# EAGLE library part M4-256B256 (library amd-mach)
AMD MACH SERIES
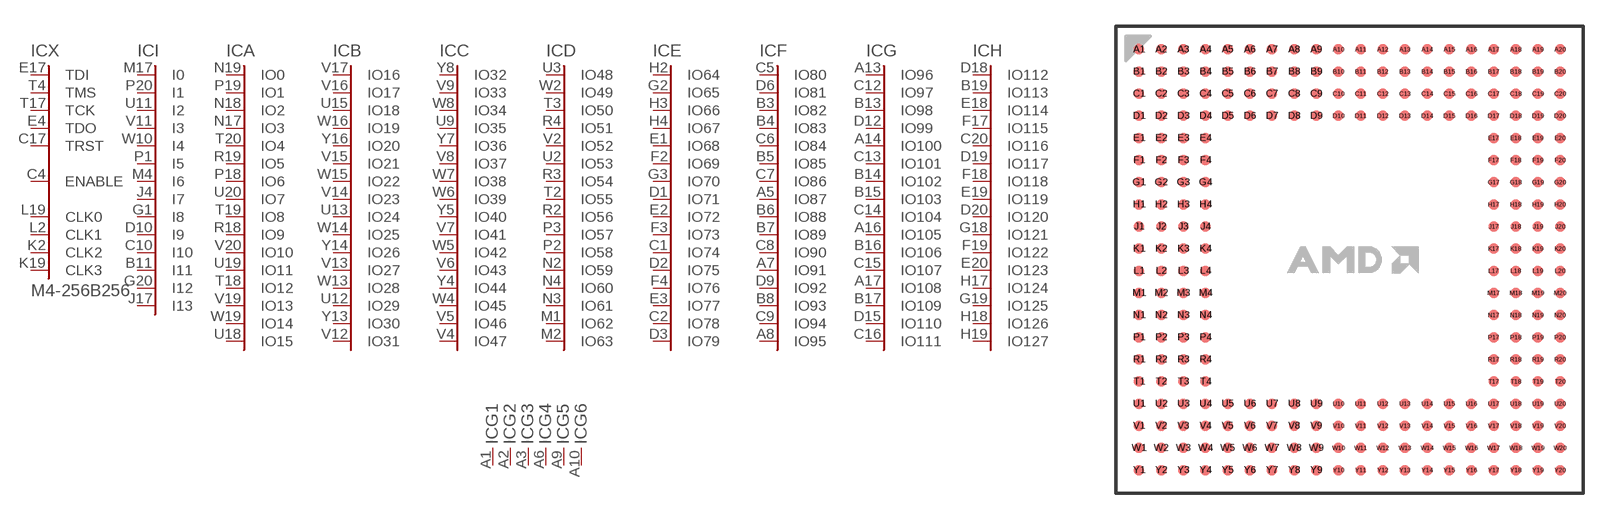
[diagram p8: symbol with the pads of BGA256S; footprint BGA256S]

Designator prefix IC; gates X=M4-256-C A=IO15 B=IO31 C=IO47 D=IO63 E=IO79 F=IO95 G=IO111 H=IO127 I=M4-I13 G1=GND G2=GND G3=GND G4=GND G5=GND G6=GND G7=GND G8=GND G9=GND G10=GND G11=GND G12=GND G13=GND G14=GND G15=GND G16=GND G17=GND G18=GND G19=GND G20=GND G21=GND G22=GND V1=VCC V2=VCC V3=VCC V4=VCC V5=VCC V6=VCC V7=VCC V8=VCC V9=VCC V10=VCC V11=VCC V12=VCC V13=VCC V14=VCC V15=VCC V16=VCC V17=VCC V18=VCC V19=VCC V20=VCC G23=GND G24=GND G25=GND G26=GND G27=GND G28=GND G29=GND G30=GND G31=GND G32=GND NC1=NC NC2=NC NC3=NC NC4=NC NC5=NC NC6=NC NC7=NC NC8=NC NC9=NC NC10=NC NC11=NC NC12=NC NC13=NC NC14=NC NC15=NC NC16=NC NC17=NC NC18=NC NC19=NC NC20=NC NC21=NC NC22=NC NC23=NC NC24=NC NC25=NC NC26=NC NC27=NC NC28=NC NC29=NC NC30=NC NC31=NC NC32=NC NC33=NC NC34=NC NC35=NC NC36=NC NC37=NC NC38=NC NC39=NC NC40=NC NC41=NC NC42=NC NC43=NC NC44=NC NC45=NC NC46=NC NC47=NC NC48=NC G33=GND G34=GND G35=GND G36=GND

## M4-256B256 (OC_FARNELL: unknown; OC_NEWARK: unknown)  [BGA256S]
A1  G1:GND  pwr
A2  G2:GND  pwr
A3  G3:GND  pwr
A4  NC1:NC  nc
A5  F:IO87
A6  G4:GND  pwr
A7  F:IO91
A8  F:IO95
A9  G5:GND  pwr
A10  G6:GND  pwr
A11  G7:GND  pwr
A12  G8:GND  pwr
A13  G:IO96
A14  G:IO100
A15  G9:GND  pwr
A16  G:IO105
A17  G:IO108
A18  G10:GND  pwr
A19  NC2:NC  nc
A20  G11:GND  pwr
B1  G12:GND  pwr
B2  NC3:NC  nc
B3  F:IO82
B4  F:IO83
B5  F:IO85
B6  F:IO88
B7  F:IO89
B8  F:IO93
B9  NC4:NC  nc
B10  NC5:NC  nc
B11  I:I11  in
B12  NC6:NC  nc
B13  G:IO98
B14  G:IO102
B15  G:IO103
B16  G:IO106
B17  G:IO109
B18  NC7:NC  nc
B19  H:IO113
B20  G13:GND  pwr
C1  E:IO74
C2  E:IO78
C3  V1:VCC  pwr
C4  X:ENABLE  in
C5  F:IO80
C6  F:IO84
C7  F:IO86
C8  F:IO90
C9  F:IO94
C10  I:I10  in
C11  NC8:NC  nc
C12  G:IO97
C13  G:IO101
C14  G:IO104
C15  G:IO107
C16  G:IO111
C17  X:TRST  in
C18  V2:VCC  pwr
C19  NC9:NC  nc
C20  H:IO116
D1  E:IO71
D2  E:IO75
D3  E:IO79
D4  V3:VCC  pwr
D5  V4:VCC  pwr
D6  F:IO81
D7  V5:VCC  pwr
D8  NC10:NC  nc
D9  F:IO92
D10  I:I9  in
D11  NC11:NC  nc
D12  G:IO99
D13  NC12:NC  nc
D14  V6:VCC  pwr
D15  G:IO110
D16  V7:VCC  pwr
D17  V8:VCC  pwr
D18  H:IO112
D19  H:IO117
D20  H:IO120
E1  E:IO68
E2  E:IO72
E3  E:IO77
E4  X:TDO  in
E17  X:TDI  in
E18  H:IO114
E19  H:IO119
E20  H:IO123
F1  G14:GND  pwr
F2  E:IO69
F3  E:IO73
F4  E:IO76
F17  H:IO115
F18  H:IO118
F19  H:IO122
F20  G15:GND  pwr
G1  I:I8  in
G2  E:IO65
G3  E:IO70
G4  V9:VCC  pwr
G17  V10:VCC  pwr
G18  H:IO121
G19  H:IO125
G20  I:I12  in
H1  G16:GND  pwr
H2  E:IO64
H3  E:IO66
H4  E:IO67
H17  H:IO124
H18  H:IO126
H19  H:IO127
H20  G17:GND  pwr
J1  NC13:NC  nc
J2  NC14:NC  nc
J3  NC15:NC  nc
J4  I:I7  in
J17  I:I13  in
J18  NC16:NC  nc
J19  NC17:NC  nc
J20  NC18:NC  nc
K1  NC19:NC  nc
K2  X:CLK2  in
K3  NC20:NC  nc
K4  NC21:NC  nc
K17  NC22:NC  nc
K18  NC23:NC  nc
K19  X:CLK3  in
K20  G18:GND  pwr
L1  G19:GND  pwr
L2  X:CLK1  in
L3  NC24:NC  nc
L4  NC25:NC  nc
L17  NC26:NC  nc
L18  NC27:NC  nc
L19  X:CLK0  in
L20  NC28:NC  nc
M1  D:IO62
M2  D:IO63
M3  NC29:NC  nc
M4  I:I6  in
M17  I:I0  in
M18  NC30:NC  nc
M19  NC31:NC  nc
M20  NC32:NC  nc
N1  G20:GND  pwr
N2  D:IO59
N3  D:IO61
N4  D:IO60
N17  A:IO3
N18  A:IO2
N19  A:IO0
N20  G21:GND  pwr
P1  I:I5  in
P2  D:IO58
P3  D:IO57
P4  V11:VCC  pwr
P17  V12:VCC  pwr
P18  A:IO6
P19  A:IO1
P20  I:I1  in
R1  G22:GND  pwr
R2  D:IO56
R3  D:IO54
R4  D:IO51
R17  NC33:NC  nc
R18  A:IO9
R19  A:IO5
R20  G23:GND  pwr
T1  NC34:NC  nc
T2  D:IO55
T3  D:IO50
T4  X:TMS  in
T17  X:TCK  in
T18  A:IO12
T19  A:IO8
T20  A:IO4
U1  NC35:NC  nc
U2  D:IO53
U3  D:IO48
U4  V13:VCC  pwr
U5  V14:VCC  pwr
U6  NC36:NC  nc
U7  V15:VCC  pwr
U8  NC37:NC  nc
U9  C:IO35
U10  NC38:NC  nc
U11  I:I2  in
U12  B:IO29
U13  B:IO24
U14  V16:VCC  pwr
U15  B:IO18
U16  V17:VCC  pwr
U17  V18:VCC  pwr
U18  A:IO15
U19  A:IO11
U20  A:IO7
V1  NC39:NC  nc
V2  D:IO52
V3  V19:VCC  pwr
V4  C:IO47
V5  C:IO46
V6  C:IO43
V7  C:IO41
V8  C:IO37
V9  C:IO33
V10  NC40:NC  nc
V11  I:I3  in
V12  B:IO31
V13  B:IO27
V14  B:IO23
V15  B:IO21
V16  B:IO17
V17  B:IO16
V18  V20:VCC  pwr
V19  A:IO13
V20  A:IO10
W1  G24:GND  pwr
W2  D:IO49
W3  NC41:NC  nc
W4  C:IO45
W5  C:IO42
W6  C:IO39
W7  C:IO38
W8  C:IO34
W9  NC42:NC  nc
W10  I:I4  in
W11  NC43:NC  nc
W12  NC44:NC  nc
W13  B:IO28
W14  B:IO25
W15  B:IO22
W16  B:IO19
W17  NC45:NC  nc
W18  NC46:NC  nc
W19  A:IO14
W20  G25:GND  pwr
Y1  G26:GND  pwr
Y2  NC47:NC  nc
Y3  G27:GND  pwr
Y4  C:IO44
Y5  C:IO40
Y6  G28:GND  pwr
Y7  C:IO36
Y8  C:IO32
Y9  G29:GND  pwr
Y10  G30:GND  pwr
Y11  G31:GND  pwr
Y12  G32:GND  pwr
Y13  B:IO30
Y14  B:IO26
Y15  G33:GND  pwr
Y16  B:IO20
Y17  NC48:NC  nc
Y18  G34:GND  pwr
Y19  G35:GND  pwr
Y20  G36:GND  pwr

## Footprint BGA256S (pad centres in mm)
Ball Grid Array square
smd 0.6 x 0.6: A1 -12.065,12.065; A2 -10.795,12.065; A3 -9.525,12.065; A4 -8.255,12.065; A5 -6.985,12.065; A6 -5.715,12.065; A7 -4.445,12.065; A8 -3.175,12.065; A9 -1.905,12.065; A10 -0.635,12.065; A11 0.635,12.065; A12 1.905,12.065; A13 3.175,12.065; A14 4.445,12.065; A15 5.715,12.065; A16 6.985,12.065; A17 8.255,12.065; A18 9.525,12.065; A19 10.795,12.065; A20 12.065,12.065; B1 -12.065,10.795; B2 -10.795,10.795; B3 -9.525,10.795; B4 -8.255,10.795; B5 -6.985,10.795; B6 -5.715,10.795; B7 -4.445,10.795; B8 -3.175,10.795; B9 -1.905,10.795; B10 -0.635,10.795; B11 0.635,10.795; B12 1.905,10.795; B13 3.175,10.795; B14 4.445,10.795; B15 5.715,10.795; B16 6.985,10.795; B17 8.255,10.795; B18 9.525,10.795; B19 10.795,10.795; B20 12.065,10.795; C1 -12.065,9.525; C2 -10.795,9.525; C3 -9.525,9.525; C4 -8.255,9.525; C5 -6.985,9.525; C6 -5.715,9.525; C7 -4.445,9.525; C8 -3.175,9.525; C9 -1.905,9.525; C10 -0.635,9.525; C11 0.635,9.525; C12 1.905,9.525; C13 3.175,9.525; C14 4.445,9.525; C15 5.715,9.525; C16 6.985,9.525; C17 8.255,9.525; C18 9.525,9.525; C19 10.795,9.525; C20 12.065,9.525; D1 -12.065,8.255; D2 -10.795,8.255; D3 -9.525,8.255; D4 -8.255,8.255; D5 -6.985,8.255; D6 -5.715,8.255; D7 -4.445,8.255; D8 -3.175,8.255; D9 -1.905,8.255; D10 -0.635,8.255; D11 0.635,8.255; D12 1.905,8.255; D13 3.175,8.255; D14 4.445,8.255; D15 5.715,8.255; D16 6.985,8.255; D17 8.255,8.255; D18 9.525,8.255; D19 10.795,8.255; D20 12.065,8.255; E1 -12.065,6.985; E2 -10.795,6.985; E3 -9.525,6.985; E4 -8.255,6.985; E17 8.255,6.985; E18 9.525,6.985; E19 10.795,6.985; E20 12.065,6.985; F1 -12.065,5.715; F2 -10.795,5.715; F3 -9.525,5.715; F4 -8.255,5.715; F17 8.255,5.715; F18 9.525,5.715; F19 10.795,5.715; F20 12.065,5.715; G1 -12.065,4.445; G2 -10.795,4.445; G3 -9.525,4.445; G4 -8.255,4.445; G17 8.255,4.445; G18 9.525,4.445; G19 10.795,4.445; G20 12.065,4.445; H1 -12.065,3.175; H2 -10.795,3.175; H3 -9.525,3.175; H4 -8.255,3.175; H17 8.255,3.175; H18 9.525,3.175; H19 10.795,3.175; H20 12.065,3.175; J1 -12.065,1.905; J2 -10.795,1.905; J3 -9.525,1.905; J4 -8.255,1.905; J17 8.255,1.905; J18 9.525,1.905; J19 10.795,1.905; J20 12.065,1.905; K1 -12.065,0.635; K2 -10.795,0.635; K3 -9.525,0.635; K4 -8.255,0.635; K17 8.255,0.635; K18 9.525,0.635; K19 10.795,0.635; K20 12.065,0.635; L1 -12.065,-0.635; L2 -10.795,-0.635; L3 -9.525,-0.635; L4 -8.255,-0.635; L17 8.255,-0.635; L18 9.525,-0.635; L19 10.795,-0.635; L20 12.065,-0.635; M1 -12.065,-1.905; M2 -10.795,-1.905; M3 -9.525,-1.905; M4 -8.255,-1.905; M17 8.255,-1.905; M18 9.525,-1.905; M19 10.795,-1.905; M20 12.065,-1.905; N1 -12.065,-3.175; N2 -10.795,-3.175; N3 -9.525,-3.175; N4 -8.255,-3.175; N17 8.255,-3.175; N18 9.525,-3.175; N19 10.795,-3.175; N20 12.065,-3.175; P1 -12.065,-4.445; P2 -10.795,-4.445; P3 -9.525,-4.445; P4 -8.255,-4.445; P17 8.255,-4.445; P18 9.525,-4.445; P19 10.795,-4.445; P20 12.065,-4.445; R1 -12.065,-5.715; R2 -10.795,-5.715; R3 -9.525,-5.715; R4 -8.255,-5.715; R17 8.255,-5.715; R18 9.525,-5.715; R19 10.795,-5.715; R20 12.065,-5.715; T1 -12.065,-6.985; T2 -10.795,-6.985; T3 -9.525,-6.985; T4 -8.255,-6.985; T17 8.255,-6.985; T18 9.525,-6.985; T19 10.795,-6.985; T20 12.065,-6.985; U1 -12.065,-8.255; U2 -10.795,-8.255; U3 -9.525,-8.255; U4 -8.255,-8.255; U5 -6.985,-8.255; U6 -5.715,-8.255; U7 -4.445,-8.255; U8 -3.175,-8.255; U9 -1.905,-8.255; U10 -0.635,-8.255; U11 0.635,-8.255; U12 1.905,-8.255; U13 3.175,-8.255; U14 4.445,-8.255; U15 5.715,-8.255; U16 6.985,-8.255; U17 8.255,-8.255; U18 9.525,-8.255; U19 10.795,-8.255; U20 12.065,-8.255; V1 -12.065,-9.525; V2 -10.795,-9.525; V3 -9.525,-9.525; V4 -8.255,-9.525; V5 -6.985,-9.525; V6 -5.715,-9.525; V7 -4.445,-9.525; V8 -3.175,-9.525; V9 -1.905,-9.525; V10 -0.635,-9.525; V11 0.635,-9.525; V12 1.905,-9.525; V13 3.175,-9.525; V14 4.445,-9.525; V15 5.715,-9.525; V16 6.985,-9.525; V17 8.255,-9.525; V18 9.525,-9.525; V19 10.795,-9.525; V20 12.065,-9.525; W1 -12.065,-10.795; W2 -10.795,-10.795; W3 -9.525,-10.795; W4 -8.255,-10.795; W5 -6.985,-10.795; W6 -5.715,-10.795; W7 -4.445,-10.795; W8 -3.175,-10.795; W9 -1.905,-10.795; W10 -0.635,-10.795; W11 0.635,-10.795; W12 1.905,-10.795; W13 3.175,-10.795; W14 4.445,-10.795; W15 5.715,-10.795; W16 6.985,-10.795; W17 8.255,-10.795; W18 9.525,-10.795; W19 10.795,-10.795; W20 12.065,-10.795; Y1 -12.065,-12.065; Y2 -10.795,-12.065; Y3 -9.525,-12.065; Y4 -8.255,-12.065; Y5 -6.985,-12.065; Y6 -5.715,-12.065; Y7 -4.445,-12.065; Y8 -3.175,-12.065; Y9 -1.905,-12.065; Y10 -0.635,-12.065; Y11 0.635,-12.065; Y12 1.905,-12.065; Y13 3.175,-12.065; Y14 4.445,-12.065; Y15 5.715,-12.065; Y16 6.985,-12.065; Y17 8.255,-12.065; Y18 9.525,-12.065; Y19 10.795,-12.065; Y20 12.065,-12.065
